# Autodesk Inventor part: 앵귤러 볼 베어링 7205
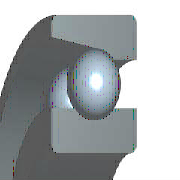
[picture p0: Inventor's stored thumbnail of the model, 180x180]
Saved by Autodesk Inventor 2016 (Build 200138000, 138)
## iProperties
Created: 2012-02
Part Number: 앵귤러 볼 베어링 7205
Material: 강철, 연강
Description: 앵귤러 콘택트 볼 베어링
Document SubType Name: Modeling
Standard: KS B 2024
Designer: mduedu
Standards Organization: KS
Language: ko-KR
Size Designation: 7205 - 25 x 52 x 15
Categories: <MemberInstance><Categories><Category DisplayName="샤프트 부품" InternalName="7f7aeb1f-a693-4053-b835-cee3144e0d98" Mnemonic="SHFT"><Category DisplayName="베어링" Inter
Density: 1 g/cm^3
Appearance: 노란색
IsCustomPart: 1
Author: mduedu
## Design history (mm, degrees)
sketch "스케치" dims "d1" = 7.02 (= -0.26 x WD + 0.26 x BD)
  geometry: L1 (3.99, 19.25)-(11.01, 19.25); L2 (7.5, 22.76)-(7.5, 15.74); L3 (0, 16.901)-(4.892, 16.901); L4 (0, 12.5)-(15, 12.5); L5 (8.11, 22.707)-(0, 24.137); L6 (15, 16.901)-(15, 12.5); L7 (15, 16.901)-(10.108, 16.901); L8 (15, 21.599)-(10.108, 21.599); L9 (15, 21.599)-(15, 26); L10 (0, 26)-(15, 26); L11 (-2.4, 0)-(14.4, 0) reference; L12 (0, -1.44)-(0, 8.99) reference; 1 further point
  constraints: 20 end point, 4 point on line, 3 symmetric about line, 2 midpoint, 2 parallel, 1 perpendicular, 14 other
  dimensions: "d0" = 10 deg angle of L8 L5; "d11" = 25 diameter of L4 L11 (= WD); "d12" = 52 diameter of L10 L11 (= BD); "d13" = 15 distance between parallel lines of L6 L12 (= KB); "d14" = 33.802 diameter of L7 L11 (= 0.326 x BD + 0.674 x WD)
revolve "본체" stored, may be unused: angle "d6" = 90 deg
revolve "볼" stored, may be unused: angle "d8" = 90 deg
pattern_circular "IDS_ARRAYBALL[SIMPL:T]" dims angle "d4" = 360 deg
body "Solid1"
fillet "모깎기1" dims "d2" = 1 (= KRS)
other parameters: "WD" = 25 [user parameter; used in 5 equation terms], "BD" = 52 [user parameter; used in 5 equation terms], "KB" = 15 [user parameter; used in 1 equation term], "KRS" = 1 [user parameter; used in 1 equation term], "d5" = 0, "d7" = 0, "d9" = 0, "d15" = 0, "d16" = 0, "BC0" = 1.02e+07 [user parameter], "BBA" = 30 deg [user parameter], "BC" = 1.56e+07 [user parameter], "KR1S" = 0.6 [user parameter], "BR" = 26 (= 0.5 x BD) [user parameter], "WR" = 12.5 (= 0.5 x WD) [user parameter]
